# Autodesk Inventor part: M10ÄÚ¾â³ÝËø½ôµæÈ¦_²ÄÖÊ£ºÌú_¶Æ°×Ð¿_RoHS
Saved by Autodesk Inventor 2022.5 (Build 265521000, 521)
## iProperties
Created: 2024-07
Part Number: M10ÄÚ¾â³ÝËø½ôµæÈ¦_²ÄÖÊ£ºÌú_¶Æ°×Ð¿_RoHS
Material: Generic
Document SubType Name: Modeling
Designer: AdminForWorker
Density: 1 g/cm^3
Appearance: Default
Title: M10ÄÚ¾â³ÝËø½ôµæÈ¦_²ÄÖÊ£ºÌú_¶Æ°×Ð¿_RoHS
Author: AdminForWorker
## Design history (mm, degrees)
feature "Body1"
body "Solid1"
